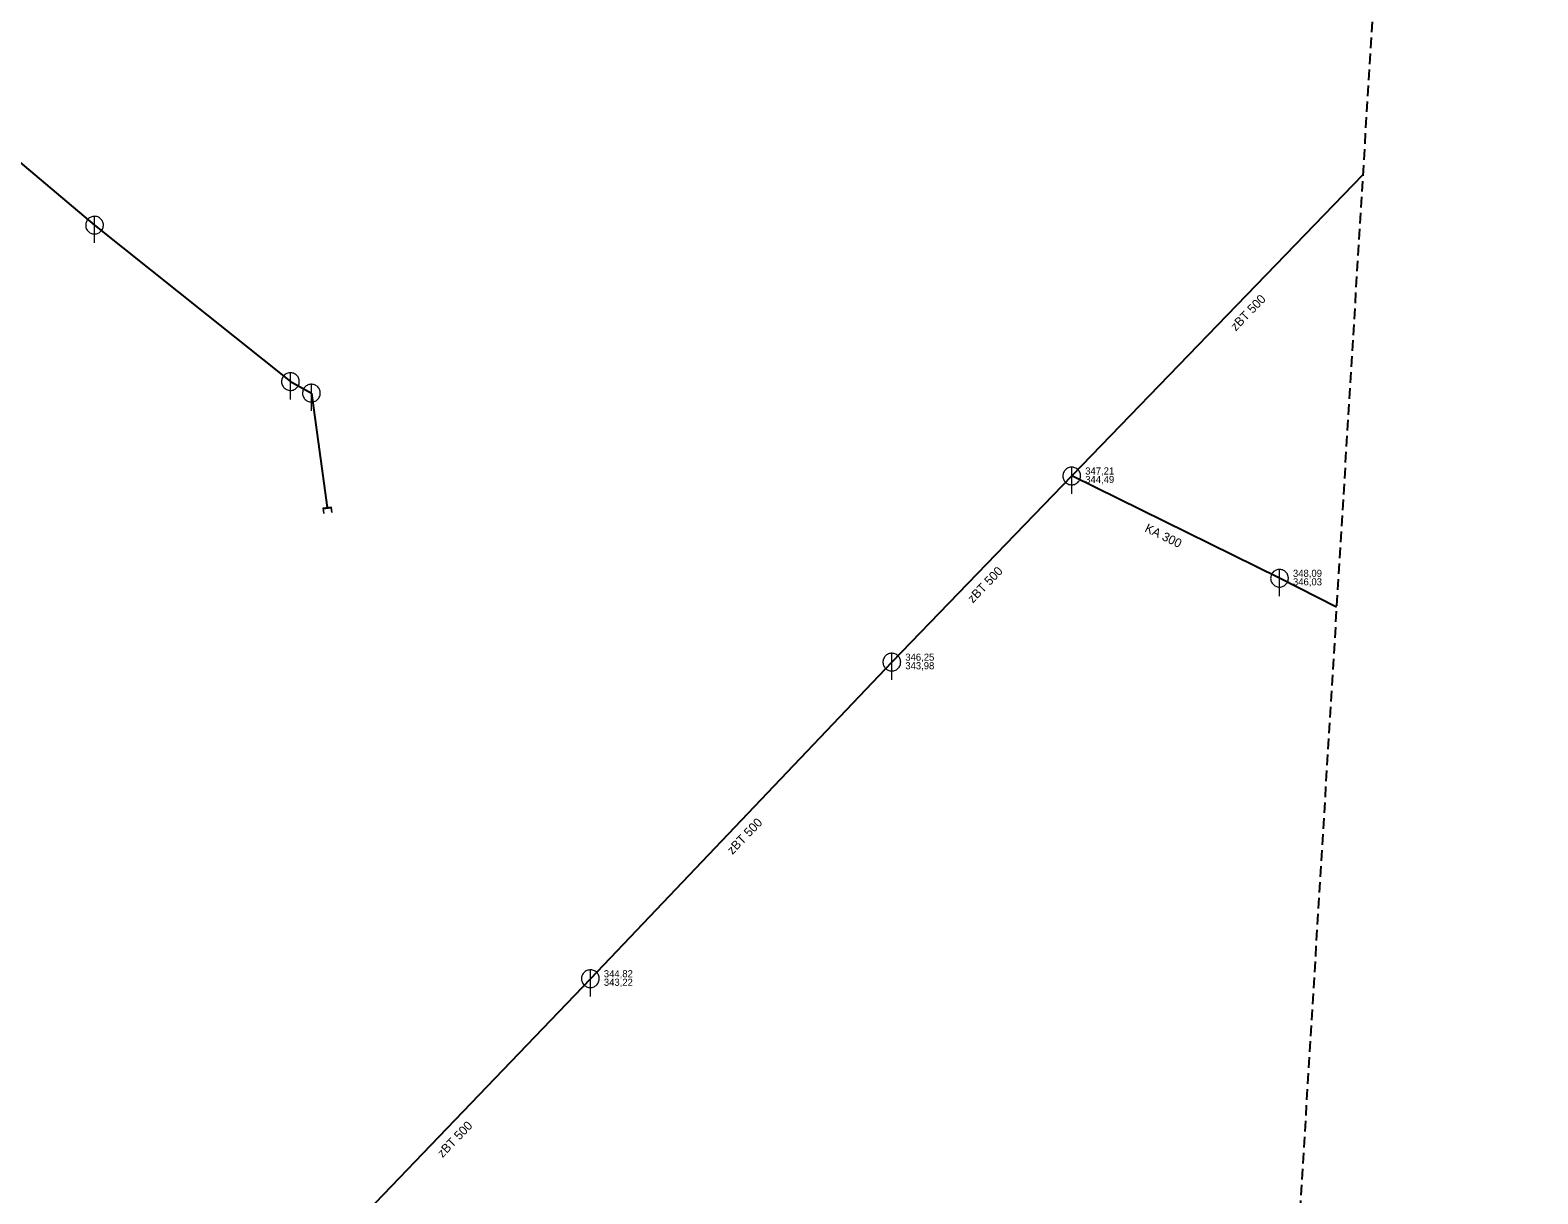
# Model space of a CAD drawing. Extents: x -724325 to -723665, y -972119 to -970722.
# Drawn here: x -724005.4 to -723835.3, y -970929.9 to -970798.6 of the extents above; entities that cross this region are included whole.
import ezdxf

# ---------------------------------------------------------------- set-up
doc = ezdxf.new("R2010")
doc.units = 0
doc.header["$LTSCALE"] = 0.4
doc.linetypes.add('MEDIUM_DASHED', pattern=[4.5, 3, -1.5])
for name, color, linetype, lineweight in [('1', 7, 'Continuous', 25), ('14', 7, 'Continuous', 25), ('22', 7, 'Continuous', 13), ('29', 7, 'Continuous', 13)]:
    doc.layers.add(name, color=color, linetype=linetype, lineweight=lineweight)
doc.layers.add('19', color=7, linetype='Continuous')

msp = doc.modelspace()

# ---------------------------------------------------------------- linework, layer by layer
at = {"layer": '1', "linetype": 'MEDIUM_DASHED'}
msp.add_lwpolyline([(-724178.033, -970726.408), (-723849.368, -970722.221), (-723876.582, -971170.211), (-723665.148, -971503.063), (-723686.082, -972118.833), (-723917.752, -972118.833), (-723962.412, -971393.118), (-724325.27, -971133.535)], close=True, dxfattribs=at)
at = {"layer": '14'}
for p, q in [((-724021.817, -970800.713), (-723998.093, -970820.63)), ((-723855.001, -970814.961), (-723887.84, -970848.91)), ((-723998.093, -970820.63), (-723975.99, -970838.27)), ((-723975.99, -970838.27), (-723973.62, -970839.57)), ((-723973.62, -970839.57), (-723971.849, -970852.479)), ((-723887.84, -970848.91), (-723908.14, -970869.91)), ((-723864.399, -970860.449), (-723887.84, -970848.91)), ((-723857.963, -970863.713), (-723864.399, -970860.449)), ((-723908.14, -970869.91), (-723942.149, -970905.61)), ((-723942.149, -970905.61), (-723973.52, -970938.289))]:
    msp.add_line(p, q, dxfattribs=at)
at = {"layer": '22'}
for p, q in [((-723998.092, -970822.629), (-723998.091, -970819.629)), ((-723975.989, -970840.27), (-723975.988, -970837.27)), ((-723973.62, -970841.57), (-723973.619, -970838.57)), ((-723887.84, -970850.91), (-723887.839, -970847.91)), ((-723864.399, -970862.449), (-723864.398, -970859.449)), ((-723908.14, -970871.91), (-723908.139, -970868.91)), ((-723942.149, -970907.61), (-723942.148, -970904.61))]:
    msp.add_line(p, q, dxfattribs=at)
for points in [[(-723997.092, -970820.629), (-723997.097, -970820.52), (-723997.115, -970820.412), (-723997.145, -970820.306), (-723997.185, -970820.205), (-723997.237, -970820.108), (-723997.299, -970820.018), (-723997.371, -970819.935), (-723997.451, -970819.861), (-723997.539, -970819.795), (-723997.633, -970819.74), (-723997.733, -970819.695), (-723997.838, -970819.662), (-723997.945, -970819.64), (-723998.054, -970819.63), (-723998.164, -970819.632), (-723998.272, -970819.646), (-723998.379, -970819.671), (-723998.482, -970819.708), (-723998.58, -970819.757), (-723998.672, -970819.815), (-723998.758, -970819.884), (-723998.835, -970819.961), (-723998.904, -970820.047), (-723998.963, -970820.139), (-723999.011, -970820.237), (-723999.048, -970820.34), (-723999.074, -970820.447), (-723999.088, -970820.555), (-723999.091, -970820.665), (-723999.081, -970820.774), (-723999.06, -970820.881), (-723999.026, -970820.985), (-723998.982, -970821.085), (-723998.927, -970821.18), (-723998.861, -970821.268), (-723998.787, -970821.348), (-723998.704, -970821.42), (-723998.614, -970821.482), (-723998.518, -970821.534), (-723998.416, -970821.575), (-723998.311, -970821.605), (-723998.203, -970821.623), (-723998.093, -970821.629), (-723997.984, -970821.623), (-723997.876, -970821.605), (-723997.771, -970821.576), (-723997.669, -970821.535), (-723997.572, -970821.483), (-723997.482, -970821.421), (-723997.399, -970821.35), (-723997.324, -970821.27), (-723997.259, -970821.182), (-723997.203, -970821.088), (-723997.159, -970820.988), (-723997.125, -970820.884), (-723997.103, -970820.776), (-723997.093, -970820.667)], [(-723974.989, -970838.27), (-723974.994, -970838.161), (-723975.012, -970838.053), (-723975.042, -970837.947), (-723975.082, -970837.846), (-723975.134, -970837.749), (-723975.196, -970837.659), (-723975.268, -970837.576), (-723975.348, -970837.502), (-723975.436, -970837.436), (-723975.53, -970837.381), (-723975.63, -970837.336), (-723975.735, -970837.303), (-723975.842, -970837.281), (-723975.951, -970837.271), (-723976.061, -970837.273), (-723976.169, -970837.287), (-723976.276, -970837.312), (-723976.379, -970837.349), (-723976.477, -970837.398), (-723976.569, -970837.456), (-723976.655, -970837.525), (-723976.732, -970837.602), (-723976.801, -970837.688), (-723976.86, -970837.78), (-723976.908, -970837.878), (-723976.945, -970837.981), (-723976.971, -970838.088), (-723976.985, -970838.196), (-723976.988, -970838.306), (-723976.978, -970838.415), (-723976.957, -970838.522), (-723976.923, -970838.626), (-723976.879, -970838.726), (-723976.824, -970838.821), (-723976.758, -970838.909), (-723976.684, -970838.989), (-723976.601, -970839.061), (-723976.511, -970839.123), (-723976.415, -970839.175), (-723976.313, -970839.216), (-723976.208, -970839.246), (-723976.1, -970839.264), (-723975.99, -970839.27), (-723975.881, -970839.264), (-723975.773, -970839.246), (-723975.668, -970839.217), (-723975.566, -970839.176), (-723975.469, -970839.124), (-723975.379, -970839.062), (-723975.296, -970838.991), (-723975.221, -970838.911), (-723975.156, -970838.823), (-723975.1, -970838.729), (-723975.056, -970838.629), (-723975.022, -970838.525), (-723975, -970838.417), (-723974.99, -970838.308)], [(-723972.62, -970839.57), (-723972.625, -970839.461), (-723972.643, -970839.353), (-723972.673, -970839.247), (-723972.713, -970839.146), (-723972.765, -970839.049), (-723972.827, -970838.959), (-723972.899, -970838.876), (-723972.979, -970838.802), (-723973.067, -970838.736), (-723973.161, -970838.681), (-723973.261, -970838.636), (-723973.366, -970838.603), (-723973.473, -970838.581), (-723973.582, -970838.571), (-723973.692, -970838.573), (-723973.8, -970838.587), (-723973.907, -970838.612), (-723974.01, -970838.649), (-723974.108, -970838.698), (-723974.2, -970838.756), (-723974.286, -970838.825), (-723974.363, -970838.902), (-723974.432, -970838.988), (-723974.491, -970839.08), (-723974.539, -970839.178), (-723974.576, -970839.281), (-723974.602, -970839.388), (-723974.616, -970839.496), (-723974.619, -970839.606), (-723974.609, -970839.715), (-723974.588, -970839.822), (-723974.554, -970839.926), (-723974.51, -970840.026), (-723974.455, -970840.121), (-723974.389, -970840.209), (-723974.315, -970840.289), (-723974.232, -970840.361), (-723974.142, -970840.423), (-723974.046, -970840.475), (-723973.944, -970840.516), (-723973.839, -970840.546), (-723973.731, -970840.564), (-723973.621, -970840.57), (-723973.512, -970840.564), (-723973.404, -970840.546), (-723973.299, -970840.517), (-723973.197, -970840.476), (-723973.1, -970840.424), (-723973.01, -970840.362), (-723972.927, -970840.291), (-723972.852, -970840.211), (-723972.787, -970840.123), (-723972.731, -970840.029), (-723972.687, -970839.929), (-723972.653, -970839.825), (-723972.631, -970839.717), (-723972.621, -970839.608)], [(-723886.84, -970848.91), (-723886.845, -970848.801), (-723886.863, -970848.693), (-723886.893, -970848.587), (-723886.933, -970848.486), (-723886.985, -970848.389), (-723887.047, -970848.299), (-723887.119, -970848.216), (-723887.199, -970848.142), (-723887.287, -970848.076), (-723887.381, -970848.021), (-723887.481, -970847.976), (-723887.586, -970847.943), (-723887.693, -970847.921), (-723887.802, -970847.911), (-723887.912, -970847.913), (-723888.02, -970847.927), (-723888.127, -970847.952), (-723888.23, -970847.989), (-723888.328, -970848.038), (-723888.42, -970848.096), (-723888.506, -970848.165), (-723888.583, -970848.242), (-723888.652, -970848.328), (-723888.711, -970848.42), (-723888.759, -970848.518), (-723888.796, -970848.621), (-723888.822, -970848.728), (-723888.836, -970848.836), (-723888.839, -970848.946), (-723888.829, -970849.055), (-723888.808, -970849.162), (-723888.774, -970849.266), (-723888.73, -970849.366), (-723888.675, -970849.461), (-723888.609, -970849.549), (-723888.535, -970849.629), (-723888.452, -970849.701), (-723888.362, -970849.763), (-723888.266, -970849.815), (-723888.164, -970849.856), (-723888.059, -970849.886), (-723887.951, -970849.904), (-723887.841, -970849.91), (-723887.732, -970849.904), (-723887.624, -970849.886), (-723887.519, -970849.857), (-723887.417, -970849.816), (-723887.32, -970849.764), (-723887.23, -970849.702), (-723887.147, -970849.631), (-723887.072, -970849.551), (-723887.007, -970849.463), (-723886.951, -970849.369), (-723886.907, -970849.269), (-723886.873, -970849.165), (-723886.851, -970849.057), (-723886.841, -970848.948)], [(-723863.399, -970860.449), (-723863.404, -970860.34), (-723863.422, -970860.232), (-723863.452, -970860.126), (-723863.492, -970860.025), (-723863.544, -970859.928), (-723863.606, -970859.838), (-723863.678, -970859.755), (-723863.758, -970859.681), (-723863.846, -970859.615), (-723863.94, -970859.56), (-723864.04, -970859.515), (-723864.145, -970859.482), (-723864.252, -970859.46), (-723864.361, -970859.45), (-723864.471, -970859.452), (-723864.579, -970859.466), (-723864.686, -970859.491), (-723864.789, -970859.528), (-723864.887, -970859.577), (-723864.979, -970859.635), (-723865.065, -970859.704), (-723865.142, -970859.781), (-723865.211, -970859.867), (-723865.27, -970859.959), (-723865.318, -970860.057), (-723865.355, -970860.16), (-723865.381, -970860.267), (-723865.395, -970860.375), (-723865.398, -970860.485), (-723865.388, -970860.594), (-723865.367, -970860.701), (-723865.333, -970860.805), (-723865.289, -970860.905), (-723865.234, -970861), (-723865.168, -970861.088), (-723865.094, -970861.168), (-723865.011, -970861.24), (-723864.921, -970861.302), (-723864.825, -970861.354), (-723864.723, -970861.395), (-723864.618, -970861.425), (-723864.51, -970861.443), (-723864.4, -970861.449), (-723864.291, -970861.443), (-723864.183, -970861.425), (-723864.078, -970861.396), (-723863.976, -970861.355), (-723863.879, -970861.303), (-723863.789, -970861.241), (-723863.706, -970861.17), (-723863.631, -970861.09), (-723863.566, -970861.002), (-723863.51, -970860.908), (-723863.466, -970860.808), (-723863.432, -970860.704), (-723863.41, -970860.596), (-723863.4, -970860.487)], [(-723907.14, -970869.91), (-723907.145, -970869.801), (-723907.163, -970869.693), (-723907.193, -970869.587), (-723907.233, -970869.486), (-723907.285, -970869.389), (-723907.347, -970869.299), (-723907.419, -970869.216), (-723907.499, -970869.142), (-723907.587, -970869.076), (-723907.681, -970869.021), (-723907.781, -970868.976), (-723907.886, -970868.943), (-723907.993, -970868.921), (-723908.102, -970868.911), (-723908.212, -970868.913), (-723908.32, -970868.927), (-723908.427, -970868.952), (-723908.53, -970868.989), (-723908.628, -970869.038), (-723908.72, -970869.096), (-723908.806, -970869.165), (-723908.883, -970869.242), (-723908.952, -970869.328), (-723909.011, -970869.42), (-723909.059, -970869.518), (-723909.096, -970869.621), (-723909.122, -970869.728), (-723909.136, -970869.836), (-723909.139, -970869.946), (-723909.129, -970870.055), (-723909.108, -970870.162), (-723909.074, -970870.266), (-723909.03, -970870.366), (-723908.975, -970870.461), (-723908.909, -970870.549), (-723908.835, -970870.629), (-723908.752, -970870.701), (-723908.662, -970870.763), (-723908.566, -970870.815), (-723908.464, -970870.856), (-723908.359, -970870.886), (-723908.251, -970870.904), (-723908.141, -970870.91), (-723908.032, -970870.904), (-723907.924, -970870.886), (-723907.819, -970870.857), (-723907.717, -970870.816), (-723907.62, -970870.764), (-723907.53, -970870.702), (-723907.447, -970870.631), (-723907.372, -970870.551), (-723907.307, -970870.463), (-723907.251, -970870.369), (-723907.207, -970870.269), (-723907.173, -970870.165), (-723907.151, -970870.057), (-723907.141, -970869.948)], [(-723941.149, -970905.61), (-723941.154, -970905.501), (-723941.172, -970905.393), (-723941.202, -970905.287), (-723941.242, -970905.186), (-723941.294, -970905.089), (-723941.356, -970904.999), (-723941.428, -970904.916), (-723941.508, -970904.842), (-723941.596, -970904.776), (-723941.69, -970904.721), (-723941.79, -970904.676), (-723941.895, -970904.643), (-723942.002, -970904.621), (-723942.111, -970904.611), (-723942.221, -970904.613), (-723942.329, -970904.627), (-723942.436, -970904.652), (-723942.539, -970904.689), (-723942.637, -970904.738), (-723942.729, -970904.796), (-723942.815, -970904.865), (-723942.892, -970904.942), (-723942.961, -970905.028), (-723943.02, -970905.12), (-723943.068, -970905.218), (-723943.105, -970905.321), (-723943.131, -970905.428), (-723943.145, -970905.536), (-723943.148, -970905.646), (-723943.138, -970905.755), (-723943.117, -970905.862), (-723943.083, -970905.966), (-723943.039, -970906.066), (-723942.984, -970906.161), (-723942.918, -970906.249), (-723942.844, -970906.329), (-723942.761, -970906.401), (-723942.671, -970906.463), (-723942.575, -970906.515), (-723942.473, -970906.556), (-723942.368, -970906.586), (-723942.26, -970906.604), (-723942.15, -970906.61), (-723942.041, -970906.604), (-723941.933, -970906.586), (-723941.828, -970906.557), (-723941.726, -970906.516), (-723941.629, -970906.464), (-723941.539, -970906.402), (-723941.456, -970906.331), (-723941.381, -970906.251), (-723941.316, -970906.163), (-723941.26, -970906.069), (-723941.216, -970905.969), (-723941.182, -970905.865), (-723941.16, -970905.757), (-723941.15, -970905.648)]]:
    msp.add_lwpolyline(points, close=True, dxfattribs=at)
at = {"layer": '29'}
for points in [[(-723971.281, -970853.037), (-723971.356, -970852.42), (-723972.341, -970852.538), (-723972.266, -970853.156)], [(-723972.18, -970853.145), (-723972.244, -970852.614), (-723971.432, -970852.517), (-723971.369, -970853.048)]]:
    msp.add_lwpolyline(points, dxfattribs=at)

# ---------------------------------------------------------------- texts
at = {"layer": '1'}
for s, rotation, p in [('zBT 500 ', 46, (-723869.326, -970832.625)), ('KA 300', 334, (-723879.688, -970855.135)), ('zBT 500 ', 46, (-723898.995, -970863.305)), ('zBT 500 ', 46, (-723926.121, -970891.663)), ('zBT 500 ', 46, (-723958.826, -970925.849))]:
    msp.add_text(s, height=1, rotation=rotation, dxfattribs=at).set_placement(p)
at = {"layer": '19'}
for s, p in [('347,21', (-723886.318, -970848.75)), ('344,49', (-723886.318, -970849.71)), ('348,09', (-723862.878, -970860.29)), ('346,03', (-723862.878, -970861.25)), ('346,25', (-723906.618, -970869.75)), ('343,98', (-723906.618, -970870.71)), ('344,82', (-723940.628, -970905.45)), ('343,22', (-723940.628, -970906.41))]:
    msp.add_text(s, height=0.8, dxfattribs=at).set_placement(p)

doc.saveas('drawing.dxf')
